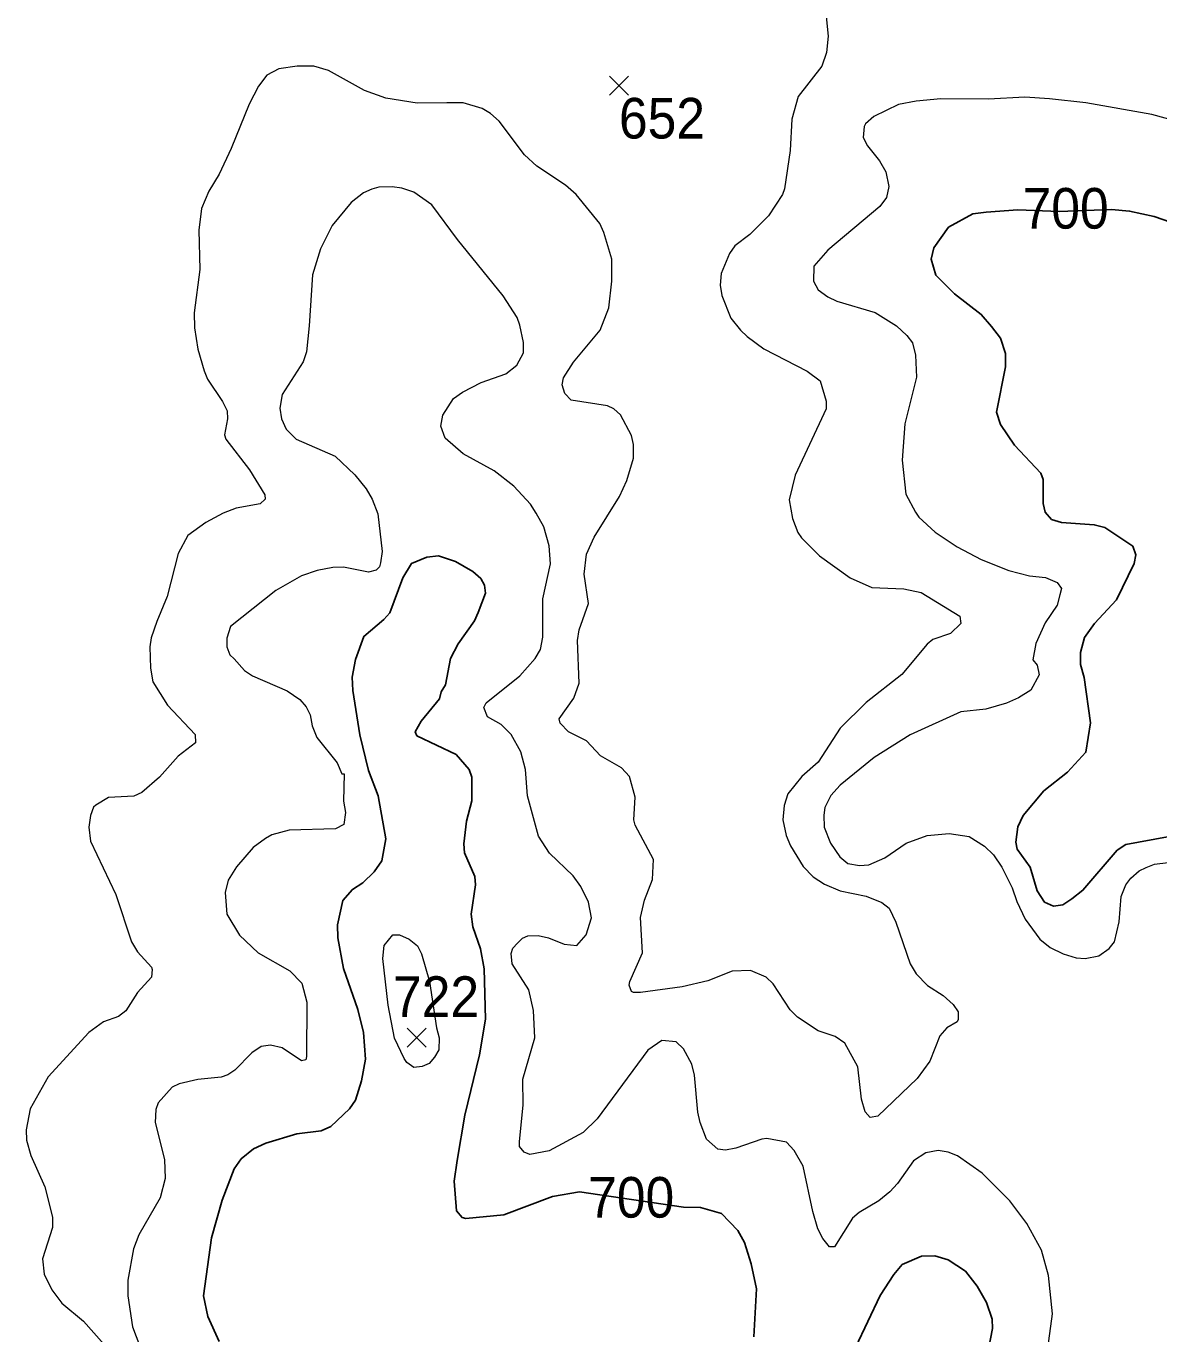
# Model space of a CAD drawing. Extents: x 294.2 to 320.3, y 7482.7 to 7510.7.
# Drawn here: x 315.279 to 317.511, y 7503.085 to 7505.662 of the extents above; entities that cross this region are included whole.
import ezdxf
from ezdxf.enums import TextEntityAlignment as Align

# ---------------------------------------------------------------- set-up
doc = ezdxf.new("R2010")
doc.units = 0
doc.header["$LTSCALE"] = 0.032
for name, color, linetype, lineweight in [('1', 7, 'Continuous', 25), ('2', 7, 'Continuous', 13), ('21', 7, 'Continuous', 25)]:
    doc.layers.add(name, color=color, linetype=linetype, lineweight=lineweight)
doc.layers.add('61', color=7, linetype='Continuous')

msp = doc.modelspace()

# ---------------------------------------------------------------- linework, layer by layer
at = {"layer": '1'}
for points in [[(317.5644, 7505.265), (317.5019, 7505.2867), (317.4534, 7505.2973), (317.4179, 7505.3003), (317.3147, 7505.2965), (317.2331, 7505.2995), (317.1708, 7505.295), (317.1443, 7505.2919), (317.0967, 7505.2655), (317.068, 7505.2247), (317.0627, 7505.2028)], [(317.0627, 7505.2028), (317.0717, 7505.1711), (317.1083, 7505.1344), (317.1612, 7505.0936), (317.1816, 7505.0702), (317.1989, 7505.0468), (317.2092, 7505.017)], [(317.2092, 7505.017), (317.2088, 7504.9903), (317.1913, 7504.9012), (317.1988, 7504.877), (317.2268, 7504.8362), (317.2784, 7504.7812), (317.283, 7504.7683), (317.283, 7504.7215), (317.2868, 7504.7041), (317.2996, 7504.6898), (317.3192, 7504.6837), (317.3838, 7504.6792), (317.4049, 7504.6739), (317.4601, 7504.6369), (317.4657, 7504.6203), (317.4626, 7504.6029), (317.4279, 7504.5312), (317.3844, 7504.4851), (317.3648, 7504.4571), (317.3564, 7504.4277), (317.3564, 7504.4043), (317.364, 7504.3786), (317.3764, 7504.2894), (317.3674, 7504.2313), (317.3314, 7504.192), (317.2845, 7504.155), (317.2437, 7504.1067), (317.2335, 7504.084), (317.229, 7504.0538), (317.232, 7504.0402), (317.2577, 7504.0047), (317.2713, 7503.9579), (317.286, 7503.936), (317.3033, 7503.9277), (317.3222, 7503.9307), (317.3396, 7503.9421), (317.3615, 7503.9594), (317.4291, 7504.038), (317.4457, 7504.0493), (317.5284, 7504.0644)], [(316.0937, 7504.3362), (316.097, 7504.3501), (316.1053, 7504.3641), (316.1153, 7504.4157), (316.1308, 7504.4447), (316.163, 7504.4899), (316.1702, 7504.5065), (316.1841, 7504.5447), (316.1824, 7504.5603), (316.1752, 7504.5732), (316.1597, 7504.5872), (316.1253, 7504.6071), (316.0915, 7504.6184), (316.0688, 7504.6152), (316.0383, 7504.6033), (316.0212, 7504.5748), (315.9959, 7504.5058), (315.9842, 7504.4924), (315.9448, 7504.4595), (315.9281, 7504.4138), (315.9215, 7504.3789), (315.9232, 7504.353), (315.9365, 7504.2653), (315.9537, 7504.1949), (315.9731, 7504.1454), (315.9881, 7504.0609), (315.9798, 7504.0173), (315.9648, 7503.9958), (315.9426, 7503.9738), (315.9221, 7503.9608), (315.9032, 7503.9388), (315.8927, 7503.8909), (315.8933, 7503.8656), (315.9049, 7503.8054), (315.9326, 7503.7242), (315.9442, 7503.6791), (315.9481, 7503.6264), (315.9403, 7503.5839), (315.9281, 7503.5457), (315.9165, 7503.529), (315.8799, 7503.4941), (315.8605, 7503.4856), (315.8128, 7503.4796), (315.7518, 7503.4614), (315.7274, 7503.4501), (315.703, 7503.4302), (315.6891, 7503.4108), (315.6653, 7503.3485), (315.6442, 7503.2743), (315.6287, 7503.1602), (315.6376, 7503.1194), (315.6598, 7503.0704)], [(316.1575, 7504.1824), (316.152, 7504.1975), (316.1264, 7504.2265), (316.0493, 7504.2636), (316.046, 7504.2711), (316.0576, 7504.2926), (316.0937, 7504.3362)], [(316.7128, 7503.0798), (316.7183, 7503.1738), (316.7077, 7503.2233), (316.6949, 7503.2652), (316.6816, 7503.2889), (316.6495, 7503.3223), (316.6079, 7503.3341), (316.5746, 7503.3352), (316.3699, 7503.3649), (316.3163, 7503.356), (316.2205, 7503.3202), (316.1454, 7503.3128), (316.1381, 7503.3149), (316.127, 7503.3278), (316.1226, 7503.3859), (316.1287, 7503.4268), (316.1438, 7503.5161), (316.1726, 7503.6349), (316.1843, 7503.7053), (316.1815, 7503.8043), (316.1742, 7503.8436), (316.1592, 7503.8872), (316.1564, 7503.9119), (316.1647, 7503.97), (316.1631, 7503.9866), (316.1431, 7504.0329), (316.142, 7504.0507), (316.147, 7504.0953), (316.1575, 7504.1356), (316.1575, 7504.1824)], [(317.1753, 7503.0555), (317.183, 7503.0959), (317.1825, 7503.1142), (317.1714, 7503.147), (317.1531, 7503.1792), (317.1304, 7503.2088), (317.0959, 7503.2314), (317.0699, 7503.2389), (317.0432, 7503.2384), (317.0056, 7503.2223), (316.9889, 7503.2024), (316.9623, 7503.161), (316.9135, 7503.0583)]]:
    msp.add_lwpolyline(points, dxfattribs=at)
at = {"layer": '2'}
for points in [[(316.8551, 7505.6874), (316.8596, 7505.6418), (316.8564, 7505.6098), (316.8468, 7505.583), (316.8002, 7505.5232), (316.7881, 7505.4786), (316.7848, 7505.4163), (316.7738, 7505.3408), (316.7698, 7505.3296), (316.7422, 7505.2878), (316.7051, 7505.251), (316.6757, 7505.2286), (316.6648, 7505.2139), (316.6489, 7505.1744), (316.647, 7505.1514), (316.6502, 7505.131), (316.668, 7505.0863), (316.6865, 7505.0626), (316.7, 7505.0505), (316.7325, 7505.0262), (316.8181, 7504.9822), (316.8436, 7504.963), (316.8558, 7504.9228), (316.8558, 7504.9075), (316.7945, 7504.7773), (316.783, 7504.7287), (316.7893, 7504.6917), (316.7996, 7504.6642), (316.8072, 7504.6533), (316.8423, 7504.6183), (316.903, 7504.5748), (316.9458, 7504.5557), (317.0084, 7504.5531), (317.0428, 7504.5461), (317.1188, 7504.4995), (317.1207, 7504.4848), (317.1003, 7504.465), (317.0658, 7504.4535), (317.0543, 7504.4439), (317.0045, 7504.3846), (316.9343, 7504.329), (316.8832, 7504.2786), (316.8398, 7504.2116)], [(315.7774, 7505.5773), (315.7537, 7505.5651), (315.7372, 7505.5434), (315.7186, 7505.5077), (315.6835, 7505.4208), (315.6593, 7505.3698), (315.6394, 7505.3366), (315.6248, 7505.3021), (315.6197, 7505.2599), (315.6216, 7505.182), (315.6101, 7505.0965), (315.6113, 7505.0671), (315.6177, 7505.025), (315.6299, 7504.9828), (315.6369, 7504.9662), (315.6663, 7504.9222), (315.6752, 7504.9037), (315.6759, 7504.8877), (315.6701, 7504.8564), (315.6726, 7504.8481), (315.7193, 7504.7875), (315.7493, 7504.7383), (315.7505, 7504.73), (315.7403, 7504.7204), (315.6931, 7504.7121), (315.6676, 7504.7019), (315.6331, 7504.684), (315.5979, 7504.6579), (315.5788, 7504.6227), (315.5571, 7504.5378), (315.5367, 7504.4887), (315.5258, 7504.4567), (315.5232, 7504.4389), (315.5245, 7504.3967), (315.529, 7504.3699), (315.5577, 7504.3239), (315.6126, 7504.2664), (315.6133, 7504.2498), (315.5788, 7504.2237), (315.5418, 7504.1822), (315.5073, 7504.1522), (315.4913, 7504.1445), (315.4415, 7504.142), (315.4166, 7504.1266), (315.4121, 7504.1228), (315.4064, 7504.1068), (315.4026, 7504.0839), (315.4058, 7504.0557), (315.4562, 7503.9511), (315.4869, 7503.8578), (315.499, 7503.838), (315.5265, 7503.808), (315.5277, 7503.8029), (315.5265, 7503.7882), (315.4984, 7503.7576), (315.476, 7503.7218), (315.4613, 7503.7103), (315.4319, 7503.7001), (315.4026, 7503.679), (315.3227, 7503.5916), (315.287, 7503.5284), (315.2793, 7503.4875), (315.28, 7503.4671), (315.2883, 7503.4365), (315.3158, 7503.3752), (315.3311, 7503.3151), (315.3311, 7503.2947), (315.3113, 7503.2334), (315.3151, 7503.2028), (315.3298, 7503.1721), (315.3496, 7503.1459), (315.3924, 7503.1102), (315.4332, 7503.0642)], [(316.0494, 7505.5096), (315.9881, 7505.5198), (315.9459, 7505.5351), (315.875, 7505.574), (315.8463, 7505.5824), (315.8131, 7505.583), (315.7774, 7505.5773)], [(317.569, 7505.468), (317.4974, 7505.4872), (317.3672, 7505.5102), (317.2957, 7505.5185), (317.2472, 7505.5217), (317.1757, 7505.5178), (317.0812, 7505.5185), (317.0326, 7505.514), (316.9982, 7505.507), (316.9496, 7505.4834), (316.933, 7505.4693), (316.9304, 7505.4636), (316.9286, 7505.4425), (316.9368, 7505.4259), (316.9609, 7505.3962), (316.9729, 7505.3744), (316.9792, 7505.3455), (316.9745, 7505.3237), (316.9611, 7505.3065), (316.8589, 7505.2203), (316.8315, 7505.189), (316.8308, 7505.1591), (316.8398, 7505.1424), (316.859, 7505.1284), (316.8768, 7505.1201), (316.9522, 7505.0977), (316.9943, 7505.0709), (317.0147, 7505.0524), (317.0256, 7505.0378), (317.0313, 7505.0135), (317.0333, 7504.9701), (317.0103, 7504.8781), (317.0052, 7504.8066), (317.0128, 7504.7395), (317.0313, 7504.7044), (317.0383, 7504.6943), (317.0703, 7504.6649), (317.1137, 7504.6361), (317.161, 7504.6112), (317.2152, 7504.5889), (317.2561, 7504.5787), (317.288, 7504.5755), (317.311, 7504.5653), (317.3193, 7504.5538), (317.3161, 7504.541), (317.3104, 7504.5212), (317.2874, 7504.4861), (317.2689, 7504.4452), (317.2631, 7504.4133), (317.2714, 7504.4024), (317.2752, 7504.384), (317.2587, 7504.3538), (317.2346, 7504.3382), (317.2111, 7504.3276), (317.1705, 7504.3162), (317.1207, 7504.3111), (317.0211, 7504.2658), (316.9502, 7504.2211), (316.8832, 7504.1662), (316.8647, 7504.1458), (316.8532, 7504.1222), (316.8507, 7504.1069), (316.8519, 7504.0838), (316.864, 7504.0519), (316.8826, 7504.0251), (316.8985, 7504.0123), (316.9215, 7504.0079), (316.9394, 7504.0092), (316.9713, 7504.0232), (317.0135, 7504.0519), (317.0543, 7504.0672), (317.0978, 7504.0711), (317.1373, 7504.0653), (317.1673, 7504.0462), (317.1852, 7504.029), (317.2018, 7504.0047)], [(316.7855, 7504.0468), (316.8104, 7504.006), (316.8302, 7503.9855), (316.8526, 7503.9714), (316.8832, 7503.9581), (316.9343, 7503.9479), (316.965, 7503.9351), (316.9796, 7503.9242), (316.993, 7503.8962), (317.0211, 7503.8144), (317.0326, 7503.7946), (317.055, 7503.7716), (317.0863, 7503.7518), (317.106, 7503.734), (317.1156, 7503.7199), (317.1156, 7503.7046), (317.1137, 7503.7001), (317.0933, 7503.688), (317.0798, 7503.6726), (317.06, 7503.6229), (317.0352, 7503.5884), (316.9573, 7503.5143), (316.942, 7503.5118), (316.9324, 7503.5226), (316.9253, 7503.5475), (316.9177, 7503.6114), (316.8921, 7503.658), (316.873, 7503.6714), (316.8398, 7503.6823), (316.7993, 7503.7091), (316.7849, 7503.7235), (316.7511, 7503.7748), (316.7375, 7503.7884), (316.7065, 7503.8012), (316.6706, 7503.7997), (316.6227, 7503.7806), (316.5717, 7503.7691), (316.4899, 7503.7582), (316.4759, 7503.7576), (316.4721, 7503.7601), (316.4676, 7503.7723), (316.4689, 7503.7793), (316.4934, 7503.8359), (316.4899, 7503.9057), (316.4975, 7503.9396), (316.5135, 7503.9804), (316.5154, 7504.02), (316.4791, 7504.0877), (316.4765, 7504.0979), (316.4791, 7504.1426), (316.4682, 7504.1835), (316.4522, 7504.2007), (316.4107, 7504.2243), (316.4018, 7504.2339), (316.3833, 7504.2537), (316.3482, 7504.2715), (316.3315, 7504.2882), (316.3297, 7504.2971), (316.3584, 7504.338), (316.3686, 7504.3674), (316.3654, 7504.4516), (316.3692, 7504.4721), (316.3871, 7504.5244), (316.3788, 7504.5819), (316.3833, 7504.6215), (316.3986, 7504.6547), (316.4484, 7504.7351), (316.4631, 7504.7664), (316.4758, 7504.8105), (316.4758, 7504.8373), (316.472, 7504.8551), (316.4503, 7504.896), (316.4375, 7504.9075), (316.4248, 7504.9138), (316.3533, 7504.9247), (316.3405, 7504.9381), (316.3354, 7504.9547), (316.3379, 7504.9688), (316.3578, 7504.9994), (316.4101, 7505.0626), (316.4273, 7505.1067), (316.4331, 7505.1591), (316.4331, 7505.2025), (316.4178, 7505.2548), (316.4094, 7505.2727), (316.3629, 7505.3302), (316.3418, 7505.348), (316.2856, 7505.3857), (316.2614, 7505.408), (316.2115, 7505.4745), (316.1943, 7505.4898), (316.1777, 7505.4994), (316.1404, 7505.5108), (316.1083, 7505.5102), (316.0494, 7505.5096)], [(316.6074, 7503.5016), (316.6029, 7503.522), (316.5959, 7503.5948), (316.5908, 7503.6165), (316.5748, 7503.6471), (316.5601, 7503.6605), (316.532, 7503.6631), (316.504, 7503.6446), (316.4043, 7503.5092), (316.3769, 7503.4824), (316.3098, 7503.446), (316.2716, 7503.439), (316.2607, 7503.4435), (316.2511, 7503.4543), (316.2511, 7503.4645), (316.2588, 7503.5361), (316.2582, 7503.5871), (316.2817, 7503.6689), (316.2792, 7503.7225), (316.2696, 7503.7634), (316.237, 7503.8144), (316.2352, 7503.8349), (316.2383, 7503.8451), (316.2473, 7503.8553), (316.2575, 7503.8648), (316.2677, 7503.8693), (316.2882, 7503.87), (316.3086, 7503.8655), (316.3392, 7503.8534), (316.3641, 7503.8508), (316.3826, 7503.8712), (316.3935, 7503.9051), (316.3871, 7503.9357), (316.3724, 7503.9664), (316.3571, 7503.9874), (316.3105, 7504.0321), (316.2888, 7504.066), (316.2671, 7504.1452), (316.2633, 7504.1975), (316.2543, 7504.232), (316.2352, 7504.2664), (316.2153, 7504.2857), (316.1883, 7504.3007), (316.1808, 7504.3191), (316.1854, 7504.3285), (316.2518, 7504.3814), (316.2824, 7504.4158), (316.2926, 7504.4337), (316.2971, 7504.458), (316.2971, 7504.5334), (316.3124, 7504.6023), (316.3098, 7504.6381), (316.299, 7504.6751), (316.2843, 7504.7019), (316.2728, 7504.7198), (316.2403, 7504.7555), (316.2013, 7504.7855), (316.1403, 7504.8191), (316.1047, 7504.8497), (316.0961, 7504.8737), (316.1004, 7504.8954), (316.1215, 7504.9279), (316.1388, 7504.9407), (316.1758, 7504.9598), (316.2245, 7504.9765), (316.2464, 7504.9937), (316.259, 7505.0182), (316.259, 7505.0383), (316.2518, 7505.0722), (316.2467, 7505.0876), (316.2192, 7505.1303), (316.1292, 7505.2414), (316.0789, 7505.3096), (316.0433, 7505.3347), (316.0192, 7505.3425), (316.0002, 7505.3447), (315.9744, 7505.3444), (315.9606, 7505.3405), (315.944, 7505.3333), (315.9197, 7505.3142), (315.8821, 7505.2689), (315.8591, 7505.2229), (315.8437, 7505.1718), (315.8368, 7505.071), (315.8317, 7505.0199), (315.8253, 7505), (315.7837, 7504.9362), (315.7793, 7504.9088), (315.7825, 7504.8883), (315.7914, 7504.8679), (315.8112, 7504.8481), (315.8881, 7504.8145), (315.9267, 7504.7779), (315.9491, 7504.7498), (315.9612, 7504.73)], [(315.9612, 7504.73), (315.9721, 7504.7006), (315.9806, 7504.6265), (315.9777, 7504.6043), (315.9754, 7504.5965), (315.9691, 7504.5898), (315.9536, 7504.5859)], [(315.9536, 7504.5859), (315.9048, 7504.5959), (315.8834, 7504.5953), (315.8527, 7504.5895), (315.8221, 7504.5787), (315.771, 7504.5499), (315.6819, 7504.4789), (315.6745, 7504.4556), (315.6745, 7504.4386), (315.6808, 7504.423), (315.6894, 7504.4152), (315.7095, 7504.3919), (315.7256, 7504.3818), (315.7933, 7504.3521), (315.8186, 7504.3348), (315.8307, 7504.3209), (315.8387, 7504.3047), (315.8431, 7504.2831), (315.8521, 7504.2601), (315.8923, 7504.2103), (315.9012, 7504.1886), (315.9057, 7504.1885), (315.9044, 7504.1349), (315.9083, 7504.1126), (315.9051, 7504.089), (315.8885, 7504.08), (315.7978, 7504.0774), (315.7633, 7504.0685), (315.7506, 7504.0615), (315.7263, 7504.0436), (315.6937, 7504.0053), (315.6771, 7503.9792), (315.6714, 7503.9549), (315.6746, 7503.9121), (315.6995, 7503.8706), (315.7365, 7503.8361), (315.7991, 7503.8004), (315.8227, 7503.7761), (315.8323, 7503.7391), (315.8317, 7503.6318), (315.8304, 7503.6254), (315.8221, 7503.6235), (315.7838, 7503.6491), (315.7608, 7503.6542), (315.7423, 7503.6516), (315.7238, 7503.6388), (315.6905, 7503.605), (315.6765, 7503.5954), (315.6637, 7503.5909), (315.6178, 7503.5865), (315.5807, 7503.5782), (315.5667, 7503.5712), (315.5392, 7503.5405), (315.5347, 7503.5271), (315.5334, 7503.5016), (315.552, 7503.4288), (315.5533, 7503.3918), (315.5431, 7503.3535), (315.5015, 7503.2807), (315.4907, 7503.2526), (315.4798, 7503.1913), (315.4798, 7503.1606), (315.4888, 7503.0993), (315.5194, 7503.0176)], [(316.8398, 7504.2116), (316.8079, 7504.1834), (316.7798, 7504.149), (316.7728, 7504.126), (316.7702, 7504.0979), (316.7766, 7504.0673), (316.7855, 7504.0468)], [(317.2018, 7504.0047), (317.2223, 7503.9638), (317.2312, 7503.937), (317.2478, 7503.9025), (317.2765, 7503.863), (317.297, 7503.8463), (317.3225, 7503.8342)], [(317.3225, 7503.8342), (317.348, 7503.8259), (317.3659, 7503.8246), (317.3927, 7503.8304), (317.4131, 7503.8444), (317.424, 7503.8578), (317.433, 7503.8974), (317.4368, 7503.9472), (317.4457, 7503.9702), (317.4559, 7503.983), (317.4725, 7503.9977), (317.486, 7504.0041), (317.5026, 7504.0104), (317.5294, 7504.0143)], [(316.7389, 7503.4703), (316.7287, 7503.469), (316.6776, 7503.4511), (316.6572, 7503.4473), (316.6419, 7503.4492), (316.6201, 7503.469), (316.6074, 7503.5016)], [(317.2925, 7503.0572), (317.3014, 7503.1249), (317.2938, 7503.2002), (317.2797, 7503.25), (317.251, 7503.303), (317.2177, 7503.3477), (317.1629, 7503.402), (317.1143, 7503.4358), (317.0958, 7503.4435), (317.0761, 7503.4466), (317.0518, 7503.4422), (317.0275, 7503.4262), (316.9962, 7503.3815), (316.9809, 7503.3649), (316.9592, 7503.3477), (316.9203, 7503.3247), (316.9075, 7503.3132), (316.8723, 7503.257), (316.8621, 7503.257), (316.8487, 7503.2736), (316.8392, 7503.2922), (316.829, 7503.3266), (316.8104, 7503.416), (316.7925, 7503.4467), (316.7772, 7503.4632), (316.7389, 7503.4703)]]:
    msp.add_lwpolyline(points, dxfattribs=at)
msp.add_lwpolyline([(316.0838, 7503.6305), (316.0736, 7503.6178), (316.0596, 7503.612), (316.0429, 7503.6101), (316.0295, 7503.6197), (316.0238, 7503.628), (316.0053, 7503.6676), (315.9925, 7503.7327), (315.9823, 7503.8246), (315.9849, 7503.8508), (316.0015, 7503.8712), (316.0149, 7503.8712), (316.0341, 7503.8629), (316.0506, 7503.8501), (316.0583, 7503.8342), (316.0739, 7503.7795), (316.0877, 7503.6886), (316.0934, 7503.6689), (316.0921, 7503.6452)], close=True, dxfattribs=at)
at = {"layer": '21'}
for p, q in [((316.4289, 7505.5633), (316.4664, 7505.5258)), ((316.4664, 7505.5633), (316.4289, 7505.5258)), ((316.0301, 7503.6879), (316.0676, 7503.6504)), ((316.0676, 7503.6879), (316.0301, 7503.6504))]:
    msp.add_line(p, q, dxfattribs=at)

# ---------------------------------------------------------------- texts
at = {"layer": '61', "width": 0.95}
for s, p in [('652', (316.5321, 7505.4402)), ('700', (317.3274, 7505.2627)), ('722', (316.087, 7503.7098)), ('700', (316.4714, 7503.3144))]:
    msp.add_text(s, height=0.08, dxfattribs=at).set_placement(p, align=Align.CENTER)

doc.saveas('drawing.dxf')
